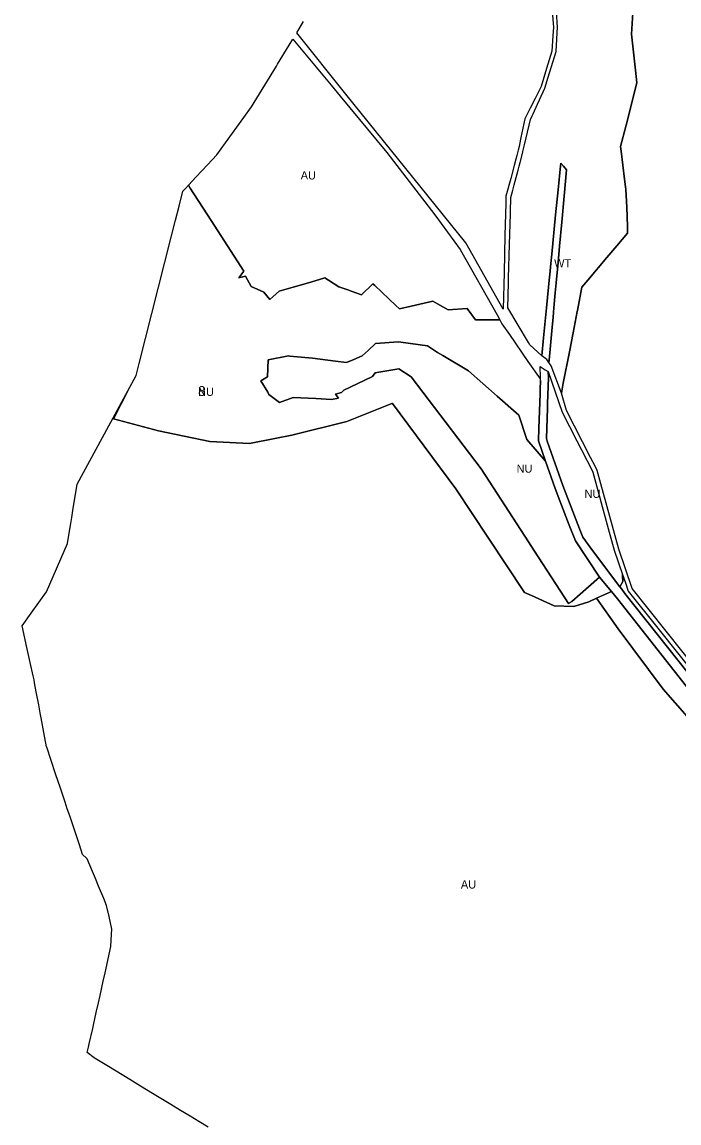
# Model space of a CAD drawing. Extents: x -537068 to -534056, y -1176840 to -1172401.
# Drawn here: x -537068 to -536666, y -1174218 to -1173545 of the extents above; entities that cross this region are included whole.
import ezdxf

# ---------------------------------------------------------------- set-up
doc = ezdxf.new("R2010")
doc.units = 0
for name, color, linetype in [('90640013', 7, 'Continuous'), ('90710013', 7, 'Continuous'), ('90710023', 7, 'Continuous'), ('90730013', 7, 'Continuous'), ('90730023', 7, 'Continuous'), ('90750013', 7, 'Continuous'), ('ID_navrh', 7, 'Continuous')]:
    doc.layers.add(name, color=color, linetype=linetype)

msp = doc.modelspace()

# ---------------------------------------------------------------- linework, layer by layer
at = {"layer": '90640013'}
msp.add_lwpolyline([(-536745.92, -1173752.89), (-536747.28, -1173750.99), (-536750.32, -1173748.72), (-536749.24, -1173737.69), (-536747.43, -1173719.3), (-536745.57, -1173700.32), (-536745.43, -1173698.9), (-536744.78, -1173692.27), (-536744.22, -1173686.61), (-536741.85, -1173662.4), (-536740.35, -1173647.13), (-536738.92, -1173632.56), (-536738.62, -1173630.78), (-536736.99, -1173632.72), (-536735.1, -1173634.97), (-536736.58, -1173651.07), (-536738.04, -1173667.04), (-536739.38, -1173681.66), (-536740.3, -1173691.71), (-536741.43, -1173704.08), (-536741.99, -1173710.19), (-536742.84, -1173719.42), (-536743.36, -1173725.12), (-536744.12, -1173733.44), (-536745.77, -1173751.42)], close=True, dxfattribs=at)
msp.add_lwpolyline([(-536651.93, -1173963.52), (-536704.04, -1173897.38), (-536707.68, -1173892.89), (-536714.87, -1173884.03), (-536729.7, -1173861.94), (-536733.45, -1173852.25), (-536739.22, -1173837.33), (-536742.13, -1173829.81), (-536748.01, -1173813.08), (-536752.33, -1173800.78), (-536752.06, -1173792.98), (-536751.34, -1173771.89), (-536751.23, -1173768.8), (-536751.08, -1173764.33), (-536750.99, -1173761.73), (-536751.28, -1173755.27), (-536748.12, -1173757.31), (-536746.46, -1173758.38), (-536746.08, -1173762.08), (-536746.68, -1173778.04), (-536746.78, -1173780.83), (-536747.48, -1173799.37), (-536746.91, -1173800.99), (-536737.4, -1173828.12), (-536727.16, -1173854.66), (-536725.23, -1173859.66), (-536719.19, -1173867.74), (-536702.47, -1173890.09), (-536701.41, -1173891.5), (-536699.42, -1173894.17), (-536647.23, -1173959.79)], dxfattribs=at)
at = {"layer": '90710013'}
for points in [[(-536694.43, -1173535.65), (-536695.35, -1173551.97), (-536695.15, -1173553.77), (-536692.92, -1173573.88), (-536692.05, -1173581.74), (-536698.67, -1173607.59), (-536702.04, -1173620.74), (-536701.68, -1173623.61), (-536699.58, -1173640.61), (-536699, -1173645.28), (-536698.8, -1173646.92), (-536698.34, -1173657.82), (-536697.84, -1173669.52), (-536697.81, -1173672.19), (-536697.8, -1173673.62), (-536704.46, -1173681.52), (-536710.47, -1173688.63), (-536722.04, -1173702.34), (-536725.71, -1173706.69), (-536728.51, -1173721.08), (-536728.63, -1173721.7), (-536731.14, -1173734.61), (-536733.42, -1173746.36), (-536737.11, -1173765.41), (-536738.3, -1173771.53), (-536744.48, -1173754.89), (-536745.92, -1173752.89), (-536745.77, -1173751.42), (-536744.12, -1173733.44), (-536743.36, -1173725.12), (-536742.84, -1173719.42), (-536741.99, -1173710.19), (-536741.43, -1173704.08), (-536740.3, -1173691.71), (-536739.38, -1173681.66), (-536738.04, -1173667.04), (-536736.58, -1173651.07), (-536735.1, -1173634.97), (-536736.99, -1173632.72), (-536738.62, -1173630.78), (-536738.92, -1173632.56), (-536740.35, -1173647.13), (-536741.85, -1173662.4), (-536744.22, -1173686.61), (-536744.78, -1173692.27), (-536745.43, -1173698.9), (-536745.57, -1173700.32), (-536747.43, -1173719.3), (-536749.24, -1173737.69), (-536750.32, -1173748.72), (-536757.48, -1173741.93), (-536758.32, -1173740.53), (-536771.08, -1173719.32), (-536770.65, -1173704.01), (-536770.6, -1173702.35), (-536770.57, -1173701.06), (-536769.99, -1173680.61), (-536769.46, -1173661.95), (-536769.43, -1173660.62), (-536769.18, -1173651.83), (-536768.01, -1173647.37), (-536767.15, -1173644.12), (-536764.76, -1173635.05), (-536764.13, -1173632.64), (-536763.55, -1173630.46), (-536761.89, -1173624.15), (-536761.8, -1173623.8), (-536760.81, -1173619.57), (-536758.04, -1173607.71), (-536757.23, -1173604.24), (-536756.13, -1173601.84), (-536755.59, -1173600.65), (-536752.9, -1173594.78), (-536749.42, -1173587.19), (-536748.45, -1173585.08), (-536746.36, -1173578.24), (-536741.57, -1173562.61), (-536740.66, -1173547.43), (-536740.8, -1173544.87), (-536741.62, -1173530.03)], [(-536743.87, -1173538.18), (-536743.18, -1173547.58), (-536743.51, -1173552.94), (-536744.08, -1173562.31), (-536747.31, -1173573.02), (-536750.59, -1173583.92), (-536754.28, -1173591.21), (-536757.32, -1173597.22), (-536759.83, -1173602.17), (-536760.6, -1173603.69), (-536763, -1173615.11), (-536763.91, -1173619.41), (-536763.98, -1173619.76), (-536764.65, -1173622.95), (-536765.52, -1173626.2), (-536766.13, -1173628.47), (-536767.15, -1173632.27), (-536769.28, -1173640.22), (-536772.2, -1173651.13), (-536772.3, -1173655.41), (-536772.79, -1173675.2), (-536773.34, -1173697.65), (-536773.89, -1173720.12), (-536796.82, -1173679.68), (-536870.03, -1173588.72), (-536900.13, -1173551.19), (-536897.15, -1173546.32), (-536895.96, -1173544.15)]]:
    msp.add_lwpolyline(points, dxfattribs=at)
msp.add_lwpolyline([(-536700.88, -1173882.54), (-536699.15, -1173887.54), (-536697.36, -1173892.73), (-536679.38, -1173915.34), (-536653.7, -1173947.64), (-536645.27, -1173958.23), (-536607.01, -1174002.55), (-536556.08, -1174061.56), (-536570.46, -1174045.5), (-536610.71, -1174000.56), (-536647.23, -1173959.79), (-536699.42, -1173894.17), (-536701.41, -1173891.5), (-536702.47, -1173890.09), (-536700.72, -1173886.71), (-536700.84, -1173883.54)], close=True, dxfattribs=at)
at = {"layer": '90710023'}
msp.add_lwpolyline([(-536531.3, -1174107.64), (-536553.25, -1174081.23), (-536591.39, -1174043.89), (-536618.92, -1174015.95), (-536645.34, -1173987.75), (-536676.1, -1173952.69), (-536703.54, -1173915.67), (-536716.72, -1173897.04), (-536707.68, -1173892.89), (-536704.04, -1173897.38), (-536651.93, -1173963.52), (-536560.66, -1174065.67), (-536545.85, -1174082.18), (-536529.27, -1174094.11), (-536525.77, -1174103.45), (-536527.4, -1174104.68)], close=True, dxfattribs=at)
at = {"layer": '90730013'}
for points in [[(-536714.87, -1173884.03), (-536721.7, -1173890.01), (-536731.89, -1173898.94), (-536732, -1173899), (-536732.55, -1173899.32), (-536734.01, -1173900.15), (-536754.68, -1173868.25), (-536760.66, -1173859.02), (-536787.3, -1173817.89), (-536830.09, -1173761.6), (-536837.77, -1173756.69), (-536849.97, -1173758.79), (-536852.1, -1173759.16), (-536853.81, -1173761.35), (-536858.57, -1173763.62), (-536867.38, -1173767.81), (-536871.29, -1173769.67), (-536872.8, -1173771.25), (-536876.37, -1173772.2), (-536874.65, -1173774.65), (-536878.89, -1173775.4), (-536888.41, -1173774.93), (-536902.39, -1173774.23), (-536910.62, -1173777.35), (-536917.12, -1173772.33), (-536917.89, -1173771.05), (-536922.12, -1173764.02), (-536917.94, -1173761.52), (-536917.53, -1173751.18), (-536905.17, -1173748.77), (-536904.38, -1173748.85), (-536890.58, -1173750.19), (-536876.38, -1173751.98), (-536869.68, -1173752.83), (-536865.19, -1173750.93), (-536860.1, -1173748.79), (-536856.5, -1173745.4), (-536852, -1173741.16), (-536837.94, -1173740.26), (-536836.39, -1173740.47), (-536820.25, -1173742.68), (-536813.97, -1173746.6), (-536810.75, -1173748.61), (-536795.16, -1173757.93), (-536777.49, -1173773.43), (-536764.31, -1173784.99), (-536759.46, -1173799.92), (-536748.01, -1173813.08), (-536742.13, -1173829.81), (-536739.22, -1173837.33), (-536733.45, -1173852.25), (-536729.7, -1173861.94)], [(-536700.88, -1173882.54), (-536700.84, -1173883.54), (-536700.72, -1173886.71), (-536702.47, -1173890.09), (-536719.19, -1173867.74), (-536725.23, -1173859.66), (-536727.16, -1173854.66), (-536737.4, -1173828.12), (-536746.91, -1173800.99), (-536747.48, -1173799.37), (-536746.78, -1173780.83), (-536746.68, -1173778.04), (-536746.08, -1173762.08), (-536746.46, -1173758.38), (-536737.9, -1173783.19), (-536728.87, -1173800.79), (-536726.06, -1173806.27), (-536719.34, -1173819.36), (-536719.02, -1173819.99), (-536709.66, -1173854.32), (-536706.01, -1173867.7)]]:
    msp.add_lwpolyline(points, close=True, dxfattribs=at)
at = {"layer": '90730023'}
msp.add_lwpolyline([(-536966.39, -1173644.41), (-536965.23, -1173646.2), (-536952.52, -1173665.92), (-536932.53, -1173696.93), (-536935.6, -1173700.95), (-536931.45, -1173700.04), (-536928.11, -1173706.3), (-536920.26, -1173709.8), (-536916.56, -1173714.28), (-536912.74, -1173710.88), (-536910.9, -1173709.24), (-536902.41, -1173706.75), (-536891.59, -1173703.57), (-536882.88, -1173701.01), (-536880.69, -1173702.42), (-536874.31, -1173706.54), (-536868.89, -1173708.43), (-536866.29, -1173709.34), (-536860.56, -1173711.34), (-536853.61, -1173704.66), (-536852.43, -1173705.78), (-536839.52, -1173717.94), (-536837.38, -1173719.95), (-536830.12, -1173718.3), (-536816.89, -1173715.3), (-536814.12, -1173716.89), (-536807.52, -1173720.67), (-536795.97, -1173719.79), (-536790.84, -1173726.67), (-536790.16, -1173726.67), (-536775.96, -1173726.62), (-536774.64, -1173729.06), (-536770.1, -1173735.75), (-536758.9, -1173752.25), (-536751.36, -1173762.78), (-536751.08, -1173764.33), (-536751.23, -1173768.8), (-536751.34, -1173771.89), (-536752.06, -1173792.98), (-536752.33, -1173800.78), (-536748.01, -1173813.08), (-536759.46, -1173799.92), (-536764.31, -1173784.99), (-536777.49, -1173773.43), (-536795.16, -1173757.93), (-536810.75, -1173748.61), (-536813.97, -1173746.6), (-536820.25, -1173742.68), (-536836.39, -1173740.47), (-536837.94, -1173740.26), (-536852, -1173741.16), (-536856.5, -1173745.4), (-536860.1, -1173748.79), (-536865.19, -1173750.93), (-536869.68, -1173752.83), (-536876.38, -1173751.98), (-536890.58, -1173750.19), (-536904.38, -1173748.85), (-536905.17, -1173748.77), (-536917.53, -1173751.18), (-536917.94, -1173761.52), (-536922.12, -1173764.02), (-536917.89, -1173771.05), (-536917.12, -1173772.33), (-536910.62, -1173777.35), (-536902.39, -1173774.23), (-536888.41, -1173774.93), (-536878.89, -1173775.4), (-536874.65, -1173774.65), (-536876.37, -1173772.2), (-536872.8, -1173771.25), (-536871.29, -1173769.67), (-536867.38, -1173767.81), (-536858.57, -1173763.62), (-536853.81, -1173761.35), (-536852.1, -1173759.16), (-536849.97, -1173758.79), (-536837.77, -1173756.69), (-536830.09, -1173761.6), (-536787.3, -1173817.89), (-536760.66, -1173859.02), (-536754.68, -1173868.25), (-536734.01, -1173900.15), (-536732.55, -1173899.32), (-536732, -1173899), (-536731.89, -1173898.94), (-536721.7, -1173890.01), (-536714.87, -1173884.03), (-536707.68, -1173892.89), (-536716.72, -1173897.04), (-536721.42, -1173899.2), (-536730.59, -1173902.07), (-536742.7, -1173901.73), (-536756.6, -1173895.44), (-536760.91, -1173893.49), (-536782.87, -1173860.22), (-536802.78, -1173830.06), (-536841.57, -1173777.83), (-536842.06, -1173777.98), (-536869.5, -1173788.82), (-536903.14, -1173797.26), (-536913.6, -1173799.22), (-536929.05, -1173802.37), (-536953.24, -1173801.18), (-536984.68, -1173794.53), (-537012.32, -1173787.26), (-537003.41, -1173770.23), (-536998.3, -1173760.8), (-536996.52, -1173753.5), (-536976.89, -1173676.04), (-536974.28, -1173665.76), (-536972.08, -1173657.08), (-536969.8, -1173648.07), (-536968.14, -1173646.29)], close=True, dxfattribs=at)
at = {"layer": '90750013'}
for points in [[(-536642.93, -1173956.37), (-536694.89, -1173891.01), (-536703.07, -1173867.09), (-536704.73, -1173861.07), (-536716.36, -1173818.81), (-536717.49, -1173816.61), (-536720.4, -1173810.93), (-536735.18, -1173782.07), (-536738.3, -1173771.53), (-536737.11, -1173765.41), (-536733.42, -1173746.36), (-536731.14, -1173734.61), (-536728.63, -1173721.7), (-536728.51, -1173721.08), (-536725.71, -1173706.69), (-536722.04, -1173702.34), (-536710.47, -1173688.63), (-536704.46, -1173681.52), (-536697.8, -1173673.62), (-536697.81, -1173672.19), (-536697.84, -1173669.52), (-536698.34, -1173657.82), (-536698.8, -1173646.92), (-536699, -1173645.28), (-536699.58, -1173640.61), (-536701.68, -1173623.61), (-536702.04, -1173620.74), (-536698.67, -1173607.59), (-536692.05, -1173581.74), (-536692.92, -1173573.88), (-536695.15, -1173553.77), (-536695.35, -1173551.97), (-536694.43, -1173535.65)], [(-536954.3, -1174220.63), (-536960.1, -1174217.1), (-536965.28, -1174213.95), (-536971.26, -1174210.32), (-536977.08, -1174206.78), (-536988.36, -1174199.93), (-536995.7, -1174195.47), (-537002.25, -1174191.49), (-537015.3, -1174183.56), (-537023.36, -1174178.67), (-537023.98, -1174178.19), (-537028.25, -1174174.91), (-537027.5, -1174171.56), (-537027.05, -1174169.54), (-537024.96, -1174160.2), (-537024.52, -1174158.23), (-537022.77, -1174150.4), (-537021.46, -1174144.53), (-537020.44, -1174139.95), (-537018.5, -1174131.29), (-537017.35, -1174126.14), (-537013.78, -1174110.15), (-537013.36, -1174102.53), (-537013.19, -1174099.53), (-537014.92, -1174091.75), (-537016.43, -1174084.93), (-537018.23, -1174080.62), (-537021.32, -1174073.22), (-537023.27, -1174068.54), (-537025.1, -1174064.15), (-537028.32, -1174056.42), (-537028.82, -1174055.94), (-537031.11, -1174053.71), (-537033.08, -1174047.82), (-537034.3, -1174044.18), (-537035.92, -1174039.36), (-537039, -1174030.17), (-537040.47, -1174025.79), (-537041.84, -1174021.72), (-537044.68, -1174013.24), (-537047.65, -1174004.36), (-537050.39, -1173996.19), (-537053.07, -1173988.2), (-537053.13, -1173987.87), (-537054.75, -1173979.24), (-537056.45, -1173970.18), (-537056.79, -1173968.35), (-537057.92, -1173962.29), (-537059.42, -1173954.27), (-537060.47, -1173948.68), (-537060.78, -1173947.01), (-537061.33, -1173944.54), (-537063.16, -1173936.34), (-537065.18, -1173927.25), (-537068.17, -1173913.84), (-537062.64, -1173906.19), (-537053.11, -1173893.02), (-537040.38, -1173863.52), (-537038.93, -1173854.77), (-537038.37, -1173851.39), (-537037.74, -1173847.62), (-537037.03, -1173843.34), (-537034.35, -1173827.25), (-537003.41, -1173770.23), (-537012.32, -1173787.26), (-536984.68, -1173794.53), (-536953.24, -1173801.18), (-536929.05, -1173802.37), (-536913.6, -1173799.22), (-536903.14, -1173797.26), (-536869.5, -1173788.82), (-536842.06, -1173777.98), (-536841.57, -1173777.83), (-536802.78, -1173830.06), (-536782.87, -1173860.22), (-536760.91, -1173893.49), (-536756.6, -1173895.44), (-536742.7, -1173901.73), (-536730.59, -1173902.07), (-536721.42, -1173899.2), (-536716.72, -1173897.04), (-536703.54, -1173915.67), (-536676.1, -1173952.69), (-536645.34, -1173987.75)]]:
    msp.add_lwpolyline(points, dxfattribs=at)
msp.add_lwpolyline([(-536966.39, -1173644.41), (-536961.6, -1173639.27), (-536954.69, -1173631.85), (-536949.07, -1173625.83), (-536943.67, -1173618.35), (-536932.52, -1173602.93), (-536927.81, -1173596.41), (-536926.19, -1173593.77), (-536919.66, -1173583.1), (-536912.55, -1173571.48), (-536911.89, -1173570.39), (-536904.71, -1173558.67), (-536902.45, -1173554.98), (-536879.11, -1173583.06), (-536873.49, -1173589.79), (-536845.07, -1173624.31), (-536815.72, -1173662.39), (-536800.26, -1173683.76), (-536777.6, -1173723.61), (-536775.96, -1173726.62), (-536790.16, -1173726.67), (-536790.84, -1173726.67), (-536795.97, -1173719.79), (-536807.52, -1173720.67), (-536814.12, -1173716.89), (-536816.89, -1173715.3), (-536830.12, -1173718.3), (-536837.38, -1173719.95), (-536839.52, -1173717.94), (-536852.43, -1173705.78), (-536853.61, -1173704.66), (-536860.56, -1173711.34), (-536866.29, -1173709.34), (-536868.89, -1173708.43), (-536874.31, -1173706.54), (-536880.69, -1173702.42), (-536882.88, -1173701.01), (-536891.59, -1173703.57), (-536902.41, -1173706.75), (-536910.9, -1173709.24), (-536912.74, -1173710.88), (-536916.56, -1173714.28), (-536920.26, -1173709.8), (-536928.11, -1173706.3), (-536931.45, -1173700.04), (-536935.6, -1173700.95), (-536932.53, -1173696.93), (-536952.52, -1173665.92), (-536965.23, -1173646.2)], close=True, dxfattribs=at)

# ---------------------------------------------------------------- texts
at = {"layer": '90640013'}
msp.add_text('WT', height=5, rotation=0, dxfattribs=at).set_placement((-536742.71, -1173694.6))
at = {"layer": '90730013'}
for rotation, p in [(360, (-536765.65, -1173820.21)), (0, (-536724.1, -1173835.63))]:
    msp.add_text('NU', height=5, rotation=rotation, dxfattribs=at).set_placement(p)
at = {"layer": '90730023'}
msp.add_text('NU', height=5, rotation=360, dxfattribs=at).set_placement((-536960.46, -1173773.24))
at = {"layer": '90750013'}
for rotation, p in [(0, (-536897.7, -1173640.83)), (360, (-536799.74, -1174074.63))]:
    msp.add_text('AU', height=5, rotation=rotation, dxfattribs=at).set_placement(p)
at = {"layer": 'ID_navrh'}
msp.add_text('8', height=6, rotation=360, dxfattribs=at).set_placement((-536960.46, -1173773.24))

doc.saveas('drawing.dxf')
